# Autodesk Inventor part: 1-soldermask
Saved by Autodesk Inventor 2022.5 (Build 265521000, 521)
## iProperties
Created: 2024-07
Part Number: 1-soldermask
Material: Generic
Document SubType Name: Modeling
Designer: AdminForWorker
Density: 1 g/cm^3
Appearance: Default
Title: 1-soldermask
Author: AdminForWorker
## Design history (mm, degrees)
feature "Body1"
body "Solid1"
